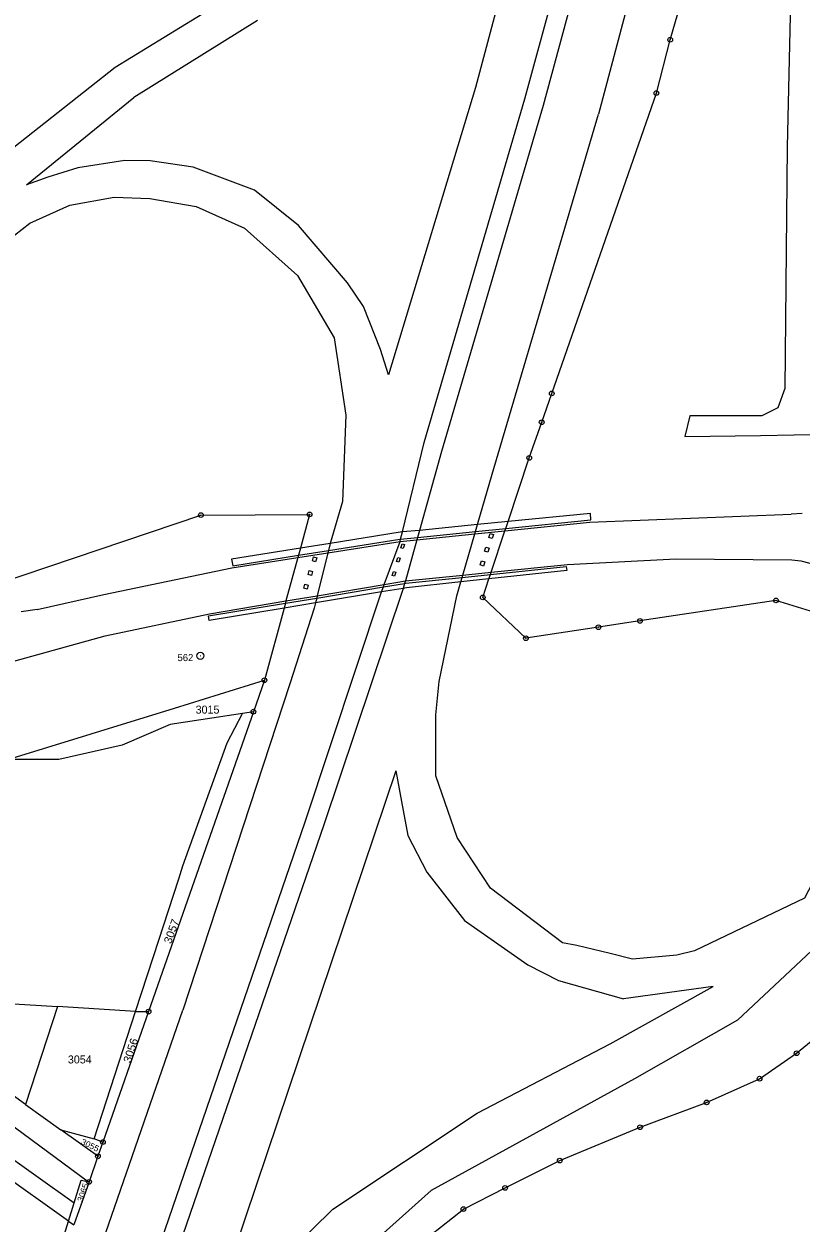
# Model space of a CAD drawing. Extents: x -606517 to -602431, y -1183120 to -1179397.
# Drawn here: x -604970.9 to -604805.8, y -1182528.7 to -1182273.9 of the extents above; entities that cross this region are included whole.
import ezdxf
from ezdxf.enums import TextEntityAlignment as Align

# ---------------------------------------------------------------- set-up
doc = ezdxf.new("R2010")
doc.units = 0
doc.header["$LTSCALE"] = 0.68
for name, color, linetype, lineweight in [('1', 7, 'Continuous', 25), ('4', 7, 'Continuous', 13), ('8', 7, 'Continuous', 25)]:
    doc.layers.add(name, color=color, linetype=linetype, lineweight=lineweight)
doc.layers.add('2', color=7, linetype='Continuous')

msp = doc.modelspace()

# ---------------------------------------------------------------- linework, layer by layer
at = {"layer": '1'}
for p, q in [((-604833.64, -1182277.28), (-604818.9, -1182226.24)), ((-604808.07, -1182269.09), (-604808.8, -1182300)), ((-604836.58, -1182288.59), (-604833.64, -1182277.28)), ((-604858.81, -1182352.43), (-604836.58, -1182288.59)), ((-604808.8, -1182300), (-604809.3, -1182351.4)), ((-604809.3, -1182351.4), (-604810.8, -1182355.5)), ((-604860.94, -1182358.55), (-604858.81, -1182352.43)), ((-604829.48, -1182357.2), (-604830.54, -1182361.56)), ((-604814.2, -1182357.2), (-604829.48, -1182357.2)), ((-604810.8, -1182355.5), (-604814.2, -1182357.2)), ((-604863.58, -1182366.11), (-604860.94, -1182358.55)), ((-604830.54, -1182361.56), (-604814.45, -1182361.33)), ((-604814.45, -1182361.33), (-604789.32, -1182360.85)), ((-604868.09, -1182379.66), (-604863.58, -1182366.11)), ((-604978.02, -1182393.33), (-604933.35, -1182378.28)), ((-604933.35, -1182378.28), (-604910.24, -1182378.12)), ((-604910.24, -1182378.12), (-604912.2, -1182385.32)), ((-604868.58, -1182381.12), (-604868.09, -1182379.66)), ((-604871.67, -1182390.4), (-604868.74, -1182381.59)), ((-604868.74, -1182381.59), (-604868.58, -1182381.12)), ((-604912.74, -1182387.28), (-604915.26, -1182396.52)), ((-604912.61, -1182386.82), (-604912.74, -1182387.28)), ((-604912.2, -1182385.32), (-604912.61, -1182386.82)), ((-604873.46, -1182395.78), (-604872.15, -1182391.84)), ((-604872.15, -1182391.84), (-604871.83, -1182390.87)), ((-604871.83, -1182390.87), (-604871.67, -1182390.4)), ((-604915.39, -1182396.99), (-604915.67, -1182398.02)), ((-604915.26, -1182396.52), (-604915.39, -1182396.99)), ((-604864.29, -1182404.43), (-604873.46, -1182395.78)), ((-604811.16, -1182396.39), (-604840.06, -1182400.76)), ((-604789.11, -1182403.23), (-604811.16, -1182396.39)), ((-604915.67, -1182398.02), (-604919.85, -1182413.35)), ((-604848.88, -1182402.1), (-604864.29, -1182404.43)), ((-604840.06, -1182400.76), (-604848.88, -1182402.1)), ((-604938.97, -1182419.26), (-604919.85, -1182413.35)), ((-604919.85, -1182413.35), (-604922.19, -1182420.04)), ((-604974.33, -1182430.2), (-604938.97, -1182419.26)), ((-604922.19, -1182420.04), (-604944.47, -1182483.77)), ((-604924.51, -1182420.46), (-604939.86, -1182422.79)), ((-604927.74, -1182426.69), (-604924.51, -1182420.46)), ((-604922.19, -1182420.04), (-604924.51, -1182420.46)), ((-604939.86, -1182422.79), (-604950.06, -1182427.16)), ((-604950.06, -1182427.16), (-604963.49, -1182430.17)), ((-604937.17, -1182452.82), (-604927.74, -1182426.69)), ((-604963.49, -1182430.17), (-604974.33, -1182430.2)), ((-604938.05, -1182455.53), (-604937.17, -1182452.82)), ((-604943.43, -1182472.04), (-604938.05, -1182455.53)), ((-604947.24, -1182483.76), (-604943.43, -1182472.04)), ((-605003.04, -1182480.19), (-604963.82, -1182482.7)), ((-604970.59, -1182503.48), (-605003.04, -1182480.19)), ((-604963.82, -1182482.7), (-604970.59, -1182503.48)), ((-604947.24, -1182483.76), (-604963.82, -1182482.7)), ((-604956.04, -1182510.8), (-604947.24, -1182483.76)), ((-604944.47, -1182483.77), (-604954.15, -1182511.48)), ((-604947.24, -1182483.76), (-604944.47, -1182483.77)), ((-604806.77, -1182492.62), (-604796.84, -1182484.35)), ((-604961.46, -1182528.28), (-605015.15, -1182490.13)), ((-604814.66, -1182498.02), (-604806.77, -1182492.62)), ((-604825.89, -1182503.06), (-604814.66, -1182498.02)), ((-604970.59, -1182503.48), (-604963.07, -1182508.88)), ((-604840.04, -1182508.34), (-604825.89, -1182503.06)), ((-604963.07, -1182508.88), (-604956.04, -1182510.8)), ((-604955.22, -1182514.52), (-604963.07, -1182508.88)), ((-604857.1, -1182515.43), (-604840.04, -1182508.34)), ((-604954.15, -1182511.48), (-604956.04, -1182510.8)), ((-604954.15, -1182511.48), (-604955.22, -1182514.52)), ((-604955.22, -1182514.52), (-604957.11, -1182519.95)), ((-604868.7, -1182521.22), (-604857.1, -1182515.43)), ((-604957.11, -1182519.95), (-604960.31, -1182529.1)), ((-604960.26, -1182524.38), (-604958.78, -1182519.57)), ((-604958.78, -1182519.57), (-604957.11, -1182519.95)), ((-604877.56, -1182525.72), (-604868.7, -1182521.22)), ((-604961.46, -1182528.28), (-604960.26, -1182524.38)), ((-604886.93, -1182533.12), (-604877.56, -1182525.72))]:
    msp.add_line(p, q, dxfattribs=at)
msp.add_lwpolyline([(-604965.59, -1182541.68), (-604961.46, -1182528.28), (-604960.31, -1182529.1)], dxfattribs=at)
at = {"layer": '4'}
for p, q in [((-604811.14, -1182151.18), (-604848.87, -1182293.06)), ((-604864.53, -1182289.85), (-604839.99, -1182200.07)), ((-604854.19, -1182209.08), (-604874.98, -1182287.4)), ((-604924.76, -1182266.71), (-604951.52, -1182283.15)), ((-604921.32, -1182273.17), (-604947.57, -1182289.52)), ((-604951.52, -1182283.15), (-604975.77, -1182302.27)), ((-604874.98, -1182287.4), (-604893.48, -1182348.49)), ((-604970.38, -1182308.08), (-604947.57, -1182289.52)), ((-604885.9, -1182362.85), (-604864.53, -1182289.85)), ((-604860.64, -1182291.24), (-604882.25, -1182364.78)), ((-604871.43, -1182369.55), (-604848.87, -1182293.06)), ((-604921.96, -1182309.26), (-604934.95, -1182304.34)), ((-604882.25, -1182364.78), (-604886.89, -1182381.51)), ((-604850.59, -1182377.95), (-604868.09, -1182379.66)), ((-604850.71, -1182379.75), (-604807.93, -1182378.05)), ((-604850.48, -1182379.3), (-604850.59, -1182377.95)), ((-604805.59, -1182377.92), (-604807.93, -1182378.05)), ((-604890.53, -1182381.86), (-604891.01, -1182381.91)), ((-604871.91, -1182382.18), (-604871.21, -1182382.38)), ((-604871.21, -1182382.38), (-604871.49, -1182383.24)), ((-604872.81, -1182385.1), (-604872.11, -1182385.3)), ((-604926.86, -1182387.67), (-604926.55, -1182389.04)), ((-604926.77, -1182389.49), (-604912.74, -1182387.28)), ((-604909.39, -1182387.14), (-604908.71, -1182387.35)), ((-604891.75, -1182388.14), (-604891.5, -1182387.31)), ((-604910.33, -1182390.06), (-604909.64, -1182390.26)), ((-604892.41, -1182390.23), (-604891.94, -1182390.38)), ((-604855.72, -1182389.19), (-604855.62, -1182390.06)), ((-604878.96, -1182395.42), (-604878.1, -1182392.48)), ((-604878.1, -1182392.48), (-604877.82, -1182391.5)), ((-604911.16, -1182443.42), (-604894.96, -1182394.6)), ((-604882.74, -1182413.64), (-604878.96, -1182395.42)), ((-604931.53, -1182399.25), (-604915.26, -1182396.52)), ((-604968.1, -1182398.34), (-604971.53, -1182398.85)), ((-604931.57, -1182400.65), (-604931.75, -1182399.7)), ((-604891.92, -1182432.59), (-604932.18, -1182551.99)), ((-604957.64, -1182542.53), (-604937.15, -1182483.49)), ((-604819.35, -1182485.58), (-604841.22, -1182498.03)), ((-605011.81, -1182487.88), (-604960.26, -1182524.38)), ((-604841.22, -1182498.03), (-604884.42, -1182521.78)), ((-604905.3, -1182525.75), (-604932.18, -1182551.99))]:
    msp.add_line(p, q, dxfattribs=at)
for points in [[(-604833.9, -1182179.84), (-604831.77, -1182180.27), (-604836.26, -1182201.16), (-604860.64, -1182291.24)], [(-604934.95, -1182304.34), (-604944.09, -1182302.97), (-604949.49, -1182302.92), (-604959.51, -1182304.46), (-604965.86, -1182306.48), (-604970.38, -1182308.08)], [(-604996.16, -1182362.56), (-604993.96, -1182351.8), (-604989.47, -1182338.91), (-604984.99, -1182330.59), (-604979.52, -1182323.91), (-604969.66, -1182316.24), (-604961.18, -1182312.41), (-604951.8, -1182310.7), (-604944.18, -1182310.98), (-604934.38, -1182312.69), (-604924.1, -1182317.34), (-604912.83, -1182327.38), (-604905, -1182340.61), (-604902.55, -1182357.01), (-604903.28, -1182375.38), (-604905.87, -1182384.3)], [(-604898.82, -1182333.94), (-604902.2, -1182328.9), (-604912.58, -1182316.74), (-604921.96, -1182309.26)], [(-604893.48, -1182348.49), (-604895.2, -1182343.08), (-604898.82, -1182333.94)], [(-604891.02, -1182383.87), (-604890.9, -1182383.36), (-604890.53, -1182381.86), (-604885.9, -1182362.85)], [(-604877.82, -1182391.5), (-604877.68, -1182391.01), (-604875.13, -1182382.25), (-604874.98, -1182381.76), (-604874.56, -1182380.3), (-604871.43, -1182369.55)], [(-604891.09, -1182383.38), (-604890.9, -1182383.36), (-604887.3, -1182383), (-604874.98, -1182381.76), (-604868.58, -1182381.12), (-604850.48, -1182379.3)], [(-604868.09, -1182379.66), (-604874.56, -1182380.3), (-604886.89, -1182381.51), (-604890.53, -1182381.86)], [(-604875.13, -1182382.25), (-604868.74, -1182381.59), (-604850.71, -1182379.75)], [(-604891.01, -1182381.91), (-604905.87, -1182384.3), (-604912.2, -1182385.32), (-604926.86, -1182387.67)], [(-604891.02, -1182383.87), (-604887.44, -1182383.5), (-604875.13, -1182382.25)], [(-604886.89, -1182381.51), (-604887.3, -1182383), (-604887.44, -1182383.5), (-604889.86, -1182392.25)], [(-604871.49, -1182383.24), (-604872.19, -1182383.04), (-604871.91, -1182382.18)], [(-604926.55, -1182389.04), (-604912.61, -1182386.82), (-604906.24, -1182385.8), (-604891.09, -1182383.38)], [(-604912.74, -1182387.28), (-604906.36, -1182386.28), (-604891.02, -1182383.87)], [(-604905.87, -1182384.3), (-604906.24, -1182385.8), (-604906.36, -1182386.28), (-604908.61, -1182395.4), (-604908.73, -1182395.89), (-604908.98, -1182396.92), (-604909.27, -1182398.08)], [(-604894.96, -1182394.6), (-604894.57, -1182393.54), (-604894.38, -1182393.01), (-604891.02, -1182383.87)], [(-604872.11, -1182385.3), (-604872.39, -1182386.15), (-604873.09, -1182385.95), (-604872.81, -1182385.1)], [(-604908.71, -1182387.35), (-604908.97, -1182388.21), (-604909.65, -1182388), (-604909.39, -1182387.14)], [(-604891.5, -1182387.31), (-604891.02, -1182387.45), (-604891.27, -1182388.28), (-604891.75, -1182388.14)], [(-604855.48, -1182388.75), (-604832.46, -1182387.55), (-604807.8, -1182387.79)], [(-604807.8, -1182387.79), (-604805.89, -1182388), (-604800.43, -1182389.41), (-604794.84, -1182393.83), (-604789.93, -1182399.11)], [(-604968.1, -1182398.34), (-604953.99, -1182395.13), (-604926.77, -1182389.49)], [(-604909.64, -1182390.26), (-604909.87, -1182391.1), (-604910.56, -1182390.9), (-604910.33, -1182390.06)], [(-604891.94, -1182390.38), (-604892.22, -1182391.24), (-604892.69, -1182391.09), (-604892.41, -1182390.23)], [(-604889.86, -1182392.25), (-604877.68, -1182391.01), (-604871.67, -1182390.4), (-604855.48, -1182388.75)], [(-604889.8, -1182392.75), (-604877.82, -1182391.5), (-604871.83, -1182390.87), (-604855.72, -1182389.19)], [(-604855.62, -1182390.06), (-604872.15, -1182391.84), (-604878.1, -1182392.48), (-604889.66, -1182393.72)], [(-604931.75, -1182399.7), (-604915.39, -1182396.99), (-604908.73, -1182395.89), (-604894.57, -1182393.54), (-604890.05, -1182392.79), (-604889.8, -1182392.75)], [(-604915.26, -1182396.52), (-604908.61, -1182395.4), (-604894.38, -1182393.01), (-604889.86, -1182392.25)], [(-604889.86, -1182392.25), (-604890.05, -1182392.79), (-604890.4, -1182393.84), (-604907.24, -1182444.1)], [(-604894.96, -1182394.6), (-604908.98, -1182396.92), (-604915.67, -1182398.02), (-604931.57, -1182400.65)], [(-604889.66, -1182393.72), (-604890.4, -1182393.84), (-604894.96, -1182394.6)], [(-605043.1, -1182431.81), (-605019.87, -1182423.25), (-604998.42, -1182416.34), (-604953.68, -1182403.94), (-604931.53, -1182399.25)], [(-604909.27, -1182398.08), (-604914.44, -1182414.15), (-604937.15, -1182483.49)], [(-604777.96, -1182408.91), (-604782.95, -1182437.12), (-604796.84, -1182464.47), (-604819.35, -1182485.58)], [(-604871.82, -1182457.55), (-604878.88, -1182446.81), (-604883.41, -1182433.68), (-604883.41, -1182420.73), (-604882.74, -1182413.64)], [(-604891.92, -1182432.59), (-604890.38, -1182441.06), (-604889.4, -1182446.35), (-604885.34, -1182454.16), (-604877.33, -1182464.4), (-604863.85, -1182473.82), (-604857.36, -1182477.17), (-604843.59, -1182481.04)], [(-604791.87, -1182434.32), (-604805.13, -1182459.7), (-604828.46, -1182470.84)], [(-604959.9, -1182592.6), (-604961.5, -1182592.05), (-604955.35, -1182572.15), (-604911.16, -1182443.42)], [(-604907.24, -1182444.1), (-604951.8, -1182573.59), (-604959.9, -1182592.6)], [(-604853.44, -1182469.71), (-604856.53, -1182469.15), (-604871.82, -1182457.55)], [(-605043.62, -1182472.73), (-605034.1, -1182470.27), (-605025.27, -1182470.42), (-605014.1, -1182475.83), (-605006.12, -1182483.34), (-604998.06, -1182489.77), (-604957.48, -1182519.72), (-604957.11, -1182519.95)], [(-604828.46, -1182470.84), (-604832.22, -1182471.79), (-604841.68, -1182472.65), (-604846.36, -1182471.39), (-604853.44, -1182469.71)], [(-604905.3, -1182525.75), (-604874.63, -1182505.32), (-604846.37, -1182490.62), (-604824.49, -1182478.42), (-604843.59, -1182481.04)], [(-604975.67, -1182672.42), (-604957.77, -1182625.67), (-604940.38, -1182584.12), (-604920.22, -1182553.88), (-604884.42, -1182521.78)]]:
    msp.add_lwpolyline(points, dxfattribs=at)
for points in [[(-604890.58, -1182384.4), (-604890.1, -1182384.55), (-604890.36, -1182385.38), (-604890.84, -1182385.23)], [(-604873.71, -1182388), (-604873.02, -1182388.22), (-604873.32, -1182389.09), (-604874.01, -1182388.87)], [(-604911.27, -1182392.96), (-604910.54, -1182393.17), (-604910.77, -1182394.04), (-604911.5, -1182393.83)]]:
    msp.add_lwpolyline(points, close=True, dxfattribs=at)
at = {"layer": '8'}
for centre, radius in [((-604833.64, -1182277.2799), 0.5), ((-604833.64, -1182277.2799), 0.0303), ((-604836.58, -1182288.5899), 0.5), ((-604836.58, -1182288.5899), 0.0303), ((-604858.81, -1182352.4299), 0.5), ((-604858.81, -1182352.4299), 0.0303), ((-604860.94, -1182358.5499), 0.5), ((-604860.94, -1182358.5499), 0.0303), ((-604863.58, -1182366.1099), 0.5), ((-604863.58, -1182366.1099), 0.0303), ((-604933.35, -1182378.2799), 0.5), ((-604933.35, -1182378.2799), 0.0303), ((-604910.24, -1182378.1199), 0.5), ((-604910.24, -1182378.1199), 0.0303), ((-604873.46, -1182395.7799), 0.5), ((-604873.46, -1182395.7799), 0.0303), ((-604811.16, -1182396.3899), 0.5), ((-604811.16, -1182396.3899), 0.0303), ((-604840.06, -1182400.7599), 0.5), ((-604848.88, -1182402.0999), 0.5), ((-604848.88, -1182402.0999), 0.0303), ((-604840.06, -1182400.7599), 0.0303), ((-604864.29, -1182404.4299), 0.5), ((-604864.29, -1182404.4299), 0.0303), ((-604933.46, -1182408.1798), 0.75), ((-604933.46, -1182408.1798), 0.03), ((-604919.85, -1182413.3499), 0.5), ((-604919.85, -1182413.3499), 0.0303), ((-604922.19, -1182420.0399), 0.5), ((-604922.19, -1182420.0399), 0.0303), ((-604944.47, -1182483.7699), 0.5), ((-604944.47, -1182483.7699), 0.0303), ((-604806.77, -1182492.6199), 0.5), ((-604806.77, -1182492.6199), 0.0303), ((-604814.66, -1182498.0199), 0.5), ((-604814.66, -1182498.0199), 0.0303), ((-604825.89, -1182503.0599), 0.5), ((-604825.89, -1182503.0599), 0.0303), ((-604840.04, -1182508.3399), 0.5), ((-604840.04, -1182508.3399), 0.0303), ((-604954.15, -1182511.4799), 0.5), ((-604954.15, -1182511.4799), 0.0303), ((-604955.22, -1182514.5199), 0.5), ((-604955.22, -1182514.5199), 0.0303), ((-604857.1, -1182515.4299), 0.5), ((-604857.1, -1182515.4299), 0.0303), ((-604957.11, -1182519.9499), 0.5), ((-604957.11, -1182519.9499), 0.0303), ((-604868.7, -1182521.2199), 0.5), ((-604868.7, -1182521.2199), 0.0303), ((-604877.56, -1182525.7199), 0.5), ((-604877.56, -1182525.7199), 0.0303)]:
    msp.add_circle(centre, radius, dxfattribs=at)

# ---------------------------------------------------------------- texts
at = {"layer": '2'}
for s, p in [('3015', (-604934.46, -1182420.455)), ('3054', (-604961.6, -1182494.785))]:
    msp.add_text(s, height=1.7, dxfattribs=at).set_placement(p)
at = {"layer": '2', "width": 1.05}
for s, height, rotation, p in [('3057', 1.7, 70, (-604939.69, -1182469.495)), ('3056', 1.7, 72, (-604948.265, -1182494.811)), ('3055', 1.27, 334, (-604958.939, -1182511.855)), ('3065', 1.27, 71, (-604958.459, -1182524.293))]:
    msp.add_text(s, height=height, rotation=rotation, dxfattribs=at).set_placement(p)
at = {"layer": '8'}
msp.add_text('562', height=1.5, dxfattribs=at).set_placement((-604934.959, -1182409.297), align=Align.RIGHT)

doc.saveas('drawing.dxf')
